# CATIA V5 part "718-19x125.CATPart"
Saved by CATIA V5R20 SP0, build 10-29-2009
Part number: 718-19x125
Definition: NONE
Nomenclature: 718-19x125
Source: Unknown
Description: 718-19x125
Bounding box of the stored display mesh (mm): x 0 to 148, y -12.5 to 12.5, z -12.5 to 12.5
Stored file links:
  C:\Users\Utente\Desktop\IO LAVORO\3D X SITO CF\X SITO\718\718-19x125.CATPart
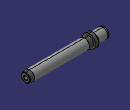
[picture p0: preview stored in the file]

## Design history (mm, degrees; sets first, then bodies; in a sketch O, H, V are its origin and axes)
Body1 "718-19x125" (main body)
  Solid1: solid without history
